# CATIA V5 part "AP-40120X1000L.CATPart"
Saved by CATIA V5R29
Part number: AP-40120X1000L
Bounding box of the stored display mesh (mm): x -500 to 500, y -60 to 60, z -20 to 20
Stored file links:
  C:\Users\Administrator\Desktop\프로젝트\Boxfold\AP-40120X1000L.CATPart
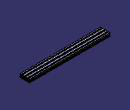
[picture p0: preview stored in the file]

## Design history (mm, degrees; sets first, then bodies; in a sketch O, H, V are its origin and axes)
Body1 (main body)
  Sketch1 on yz-plane, origin (0, 0, 0), H (0, 1, 0), V (0, 0, 1)
    point P1 (-60, -19)
    circle A1 centre (53.5, -13.5) radius 4
    circle A2 centre (53.5, 13.5) radius 4
    circle A3 centre (-53.5, -13.5) radius 4
    circle A4 centre (-53.5, 13.5) radius 4
    arc A5 centre (-38.0088, -3.1185) radius 0.3 from (-37.7966, -2.9064) to (-38.1702, -2.8656) ccw
    line L1 (-37.7966, -2.9064) -> (-37.1018, -3.6012)
    arc A6 centre (-36.8897, -3.3891) radius 0.3 from (-37.1018, -3.6012) to (-36.6868, -3.6101) ccw
    arc A7 centre (-40, 0) radius 4.9 from (-36.6868, -3.6101) to (-36.3857, -3.3086) ccw
    arc A8 centre (-36.607, -3.106) radius 0.3 from (-36.3857, -3.3086) to (-36.3949, -2.8939) ccw
    line L2 (-36.3949, -2.8939) -> (-37.0904, -2.1983)
    arc A9 centre (-36.8783, -1.9862) radius 0.3 from (-37.1314, -1.8252) to (-37.0904, -2.1983) ccw
    arc A10 centre (-40, 0) radius 3.4 from (-37.1314, -1.8252) to (-37.1323, 1.8265) ccw
    arc A11 centre (-36.8792, 1.9877) radius 0.3 from (-37.0914, 2.1998) to (-37.1323, 1.8265) ccw
    line L3 (-37.0914, 2.1998) -> (-36.396, 2.8952)
    arc A12 centre (-36.6081, 3.1073) radius 0.3 from (-36.396, 2.8952) to (-36.3869, 3.31) ccw
    arc A13 centre (-40, 0) radius 4.9 from (-36.3869, 3.31) to (-36.6881, 3.6113) ccw
    arc A14 centre (-36.8909, 3.3902) radius 0.3 from (-36.6881, 3.6113) to (-37.103, 3.6024) ccw
    line L4 (-37.103, 3.6024) -> (-37.7981, 2.9073)
    arc A15 centre (-38.0102, 3.1194) radius 0.3 from (-38.1716, 2.8665) to (-37.7981, 2.9073) ccw
    arc A16 centre (-40, 0) radius 3.4 from (-38.1716, 2.8665) to (-41.8252, 2.8686) ccw
    arc A17 centre (-41.9862, 3.1217) radius 0.3 from (-42.1983, 2.9096) to (-41.8252, 2.8686) ccw
    line L5 (-42.1983, 2.9096) -> (-42.8939, 3.6051)
    arc A18 centre (-43.106, 3.393) radius 0.3 from (-42.8939, 3.6051) to (-43.3086, 3.6143) ccw
    arc A19 centre (-40, 0) radius 4.9 from (-43.3086, 3.6143) to (-43.6101, 3.3132) ccw
    arc A20 centre (-43.3891, 3.1103) radius 0.3 from (-43.6101, 3.3132) to (-43.6012, 2.8982) ccw
    line L6 (-43.6012, 2.8982) -> (-42.9064, 2.2034)
    arc A21 centre (-43.1185, 1.9912) radius 0.3 from (-42.8656, 1.8298) to (-42.9064, 2.2034) ccw
    arc A22 centre (-40, 0) radius 3.4 from (-42.8656, 1.8298) to (-42.8665, -1.8284) ccw
    arc A23 centre (-43.1194, -1.9898) radius 0.3 from (-42.9073, -2.2019) to (-42.8665, -1.8284) ccw
    line L7 (-42.9073, -2.2019) -> (-43.6024, -2.897)
    arc A24 centre (-43.3902, -3.1091) radius 0.3 from (-43.6024, -2.897) to (-43.6113, -3.3119) ccw
    arc A25 centre (-40, 0) radius 4.9 from (-43.6113, -3.3119) to (-43.31, -3.6131) ccw
    arc A26 centre (-43.1073, -3.3919) radius 0.3 from (-43.31, -3.6131) to (-42.8952, -3.604) ccw
    line L8 (-42.8952, -3.604) -> (-42.1998, -2.9086)
    arc A27 centre (-41.9877, -3.1208) radius 0.3 from (-41.8265, -2.8677) to (-42.1998, -2.9086) ccw
    arc A28 centre (-40, 0) radius 3.4 from (-41.8265, -2.8677) to (-38.1702, -2.8656) ccw
    line L9 (39.6951, 6.0049) -> (40, 5.7)
    line L10 (40, 5.7) -> (40.3049, 6.0049)
    arc A29 centre (40, 15.5) radius 9.5 from (40.3049, 6.0049) to (47.0734, 9.1583) ccw
    arc A30 centre (46.85, 9.3585) radius 0.3 from (47.0734, 9.1583) to (47.15, 9.3585) ccw
    line L11 (47.15, 9.3585) -> (47.15, 15.7)
    arc A31 centre (46.85, 15.7) radius 0.3 from (47.15, 15.7) to (46.85, 16) ccw
    line L12 (46.85, 16) -> (44.65, 16)
    arc A32 centre (44.65, 16.5) radius 0.5 from (44.15, 16.5) to (44.65, 16) ccw
    line L13 (44.15, 16.5) -> (44.15, 19.5)
    arc A33 centre (44.65, 19.5) radius 0.5 from (44.65, 20) to (44.15, 19.5) ccw
    line L14 (44.65, 20) -> (59, 20)
    arc A34 centre (59, 19) radius 1 from (60, 19) to (59, 20) ccw
    line L15 (60, 19) -> (60, 4.65)
    arc A35 centre (59.5, 4.65) radius 0.5 from (59.5, 4.15) to (60, 4.65) ccw
    line L16 (59.5, 4.15) -> (56.5, 4.15)
    arc A36 centre (56.5, 4.65) radius 0.5 from (56, 4.65) to (56.5, 4.15) ccw
    line L17 (56, 4.65) -> (56, 6.85)
    arc A37 centre (55.7, 6.85) radius 0.3 from (56, 6.85) to (55.7, 7.15) ccw
    line L18 (55.7, 7.15) -> (49.3585, 7.15)
    arc A38 centre (49.3585, 6.85) radius 0.3 from (49.3585, 7.15) to (49.1583, 7.0734) ccw
    arc A39 centre (55.5, 0) radius 9.5 from (49.1583, 7.0734) to (46.0049, 0.3049) ccw
    line L19 (46.0049, 0.3049) -> (45.7, 0)
    line L20 (45.7, 0) -> (46.0049, -0.3049)
    arc A40 centre (55.5, 0) radius 9.5 from (46.0049, -0.3049) to (49.1583, -7.0734) ccw
    arc A41 centre (49.3585, -6.85) radius 0.3 from (49.1583, -7.0734) to (49.3585, -7.15) ccw
    line L21 (49.3585, -7.15) -> (55.7, -7.15)
    arc A42 centre (55.7, -6.85) radius 0.3 from (55.7, -7.15) to (56, -6.85) ccw
    line L22 (56, -6.85) -> (56, -4.65)
    arc A43 centre (56.5, -4.65) radius 0.5 from (56.5, -4.15) to (56, -4.65) ccw
    line L23 (56.5, -4.15) -> (59.5, -4.15)
    arc A44 centre (59.5, -4.65) radius 0.5 from (60, -4.65) to (59.5, -4.15) ccw
    line L24 (60, -4.65) -> (60, -19)
    arc A45 centre (59, -19) radius 1 from (59, -20) to (60, -19) ccw
    line L25 (59, -20) -> (44.65, -20)
    arc A46 centre (44.65, -19.5) radius 0.5 from (44.15, -19.5) to (44.65, -20) ccw
    line L26 (44.15, -19.5) -> (44.15, -16.5)
    arc A47 centre (44.65, -16.5) radius 0.5 from (44.65, -16) to (44.15, -16.5) ccw
    line L27 (44.65, -16) -> (46.85, -16)
    arc A48 centre (46.85, -15.7) radius 0.3 from (46.85, -16) to (47.15, -15.7) ccw
    line L28 (47.15, -15.7) -> (47.15, -9.3585)
    arc A49 centre (46.85, -9.3585) radius 0.3 from (47.15, -9.3585) to (47.0734, -9.1583) ccw
    arc A50 centre (40, -15.5) radius 9.5 from (47.0734, -9.1583) to (40.3049, -6.0049) ccw
    line L29 (40.3049, -6.0049) -> (40, -5.7)
    line L30 (40, -5.7) -> (39.6951, -6.0049)
    arc A51 centre (40, -15.5) radius 9.5 from (39.6951, -6.0049) to (32.9266, -9.1583) ccw
    arc A52 centre (33.15, -9.3585) radius 0.3 from (32.9266, -9.1583) to (32.85, -9.3585) ccw
    line L31 (32.85, -9.3585) -> (32.85, -15.7)
    arc A53 centre (33.15, -15.7) radius 0.3 from (32.85, -15.7) to (33.15, -16) ccw
    line L32 (33.15, -16) -> (35.35, -16)
    arc A54 centre (35.35, -16.5) radius 0.5 from (35.85, -16.5) to (35.35, -16) ccw
    line L33 (35.85, -16.5) -> (35.85, -19.5)
    arc A55 centre (35.35, -19.5) radius 0.5 from (35.35, -20) to (35.85, -19.5) ccw
    line L34 (35.35, -20) -> (4.65, -20)
    arc A56 centre (4.65, -19.5) radius 0.5 from (4.15, -19.5) to (4.65, -20) ccw
    line L35 (4.15, -19.5) -> (4.15, -16.5)
    arc A57 centre (4.65, -16.5) radius 0.5 from (4.65, -16) to (4.15, -16.5) ccw
    line L36 (4.65, -16) -> (6.85, -16)
    arc A58 centre (6.85, -15.7) radius 0.3 from (6.85, -16) to (7.15, -15.7) ccw
    line L37 (7.15, -15.7) -> (7.15, -9.3585)
    arc A59 centre (6.85, -9.3585) radius 0.3 from (7.15, -9.3585) to (7.0734, -9.1583) ccw
    arc A60 centre (0, -15.5) radius 9.5 from (7.0734, -9.1583) to (0.3049, -6.0049) ccw
    line L38 (0.3049, -6.0049) -> (0, -5.7)
    line L39 (0, -5.7) -> (-0.3049, -6.0049)
    arc A61 centre (0, -15.5) radius 9.5 from (-0.3049, -6.0049) to (-7.0734, -9.1583) ccw
    arc A62 centre (-6.85, -9.3585) radius 0.3 from (-7.0734, -9.1583) to (-7.15, -9.3585) ccw
    line L40 (-7.15, -9.3585) -> (-7.15, -15.7)
    arc A63 centre (-6.85, -15.7) radius 0.3 from (-7.15, -15.7) to (-6.85, -16) ccw
    line L41 (-6.85, -16) -> (-4.65, -16)
    arc A64 centre (-4.65, -16.5) radius 0.5 from (-4.15, -16.5) to (-4.65, -16) ccw
    line L42 (-4.15, -16.5) -> (-4.15, -19.5)
    arc A65 centre (-4.65, -19.5) radius 0.5 from (-4.65, -20) to (-4.15, -19.5) ccw
    line L43 (-4.65, -20) -> (-35.35, -20)
    arc A66 centre (-35.35, -19.5) radius 0.5 from (-35.85, -19.5) to (-35.35, -20) ccw
    line L44 (-35.85, -19.5) -> (-35.85, -16.5)
    arc A67 centre (-35.35, -16.5) radius 0.5 from (-35.35, -16) to (-35.85, -16.5) ccw
    line L45 (-35.35, -16) -> (-33.15, -16)
    arc A68 centre (-33.15, -15.7) radius 0.3 from (-33.15, -16) to (-32.85, -15.7) ccw
    line L46 (-32.85, -15.7) -> (-32.85, -9.3585)
    arc A69 centre (-33.15, -9.3585) radius 0.3 from (-32.85, -9.3585) to (-32.9266, -9.1583) ccw
    arc A70 centre (-40, -15.5) radius 9.5 from (-32.9266, -9.1583) to (-39.6951, -6.0049) ccw
    line L47 (-39.6951, -6.0049) -> (-40, -5.7)
    line L48 (-40, -5.7) -> (-40.3049, -6.0049)
    arc A71 centre (-40, -15.5) radius 9.5 from (-40.3049, -6.0049) to (-47.0734, -9.1583) ccw
    arc A72 centre (-46.85, -9.3585) radius 0.3 from (-47.0734, -9.1583) to (-47.15, -9.3585) ccw
    line L49 (-47.15, -9.3585) -> (-47.15, -15.7)
    arc A73 centre (-46.85, -15.7) radius 0.3 from (-47.15, -15.7) to (-46.85, -16) ccw
    line L50 (-46.85, -16) -> (-44.65, -16)
    arc A74 centre (-44.65, -16.5) radius 0.5 from (-44.15, -16.5) to (-44.65, -16) ccw
    line L51 (-44.15, -16.5) -> (-44.15, -19.5)
    arc A75 centre (-44.65, -19.5) radius 0.5 from (-44.65, -20) to (-44.15, -19.5) ccw
    line L52 (-44.65, -20) -> (-58, -20)
    line L53 (-58, -20) -> (-59, -20)
    arc A76 centre (-59, -19) radius 1 from (-60, -19) to (-59, -20) ccw
    line L54 (-60, -19) -> (-60, -4.65)
    arc A77 centre (-59.5, -4.65) radius 0.5 from (-59.5, -4.15) to (-60, -4.65) ccw
    line L55 (-59.5, -4.15) -> (-56.5, -4.15)
    arc A78 centre (-56.5, -4.65) radius 0.5 from (-56, -4.65) to (-56.5, -4.15) ccw
    line L56 (-56, -4.65) -> (-56, -6.85)
    arc A79 centre (-55.7, -6.85) radius 0.3 from (-56, -6.85) to (-55.7, -7.15) ccw
    line L57 (-55.7, -7.15) -> (-49.3585, -7.15)
    arc A80 centre (-49.3585, -6.85) radius 0.3 from (-49.3585, -7.15) to (-49.1583, -7.0734) ccw
    arc A81 centre (-55.5, 0) radius 9.5 from (-49.1583, -7.0734) to (-46.0049, -0.3049) ccw
    line L58 (-46.0049, -0.3049) -> (-45.7, 0)
    line L59 (-45.7, 0) -> (-46.0049, 0.3049)
    arc A82 centre (-55.5, 0) radius 9.5 from (-46.0049, 0.3049) to (-49.1583, 7.0734) ccw
    arc A83 centre (-49.3585, 6.85) radius 0.3 from (-49.1583, 7.0734) to (-49.3585, 7.15) ccw
    line L60 (-49.3585, 7.15) -> (-55.7, 7.15)
    arc A84 centre (-55.7, 6.85) radius 0.3 from (-55.7, 7.15) to (-56, 6.85) ccw
    line L61 (-56, 6.85) -> (-56, 4.65)
    arc A85 centre (-56.5, 4.65) radius 0.5 from (-56.5, 4.15) to (-56, 4.65) ccw
    line L62 (-56.5, 4.15) -> (-59.5, 4.15)
    arc A86 centre (-59.5, 4.65) radius 0.5 from (-60, 4.65) to (-59.5, 4.15) ccw
    line L63 (-60, 4.65) -> (-60, 19)
    arc A87 centre (-59, 19) radius 1 from (-59, 20) to (-60, 19) ccw
    line L64 (-59, 20) -> (-58, 20)
    line L65 (-58, 20) -> (-44.65, 20)
    arc A88 centre (-44.65, 19.5) radius 0.5 from (-44.15, 19.5) to (-44.65, 20) ccw
    line L66 (-44.15, 19.5) -> (-44.15, 16.5)
    arc A89 centre (-44.65, 16.5) radius 0.5 from (-44.65, 16) to (-44.15, 16.5) ccw
    line L67 (-44.65, 16) -> (-46.85, 16)
    arc A90 centre (-46.85, 15.7) radius 0.3 from (-46.85, 16) to (-47.15, 15.7) ccw
    line L68 (-47.15, 15.7) -> (-47.15, 9.3585)
    arc A91 centre (-46.85, 9.3585) radius 0.3 from (-47.15, 9.3585) to (-47.0734, 9.1583) ccw
    arc A92 centre (-40, 15.5) radius 9.5 from (-47.0734, 9.1583) to (-40.3049, 6.0049) ccw
    line L69 (-40.3049, 6.0049) -> (-40, 5.7)
    line L70 (-40, 5.7) -> (-39.6951, 6.0049)
    arc A93 centre (-40, 15.5) radius 9.5 from (-39.6951, 6.0049) to (-32.9266, 9.1583) ccw
    arc A94 centre (-33.15, 9.3585) radius 0.3 from (-32.9266, 9.1583) to (-32.85, 9.3585) ccw
    line L71 (-32.85, 9.3585) -> (-32.85, 15.7)
    arc A95 centre (-33.15, 15.7) radius 0.3 from (-32.85, 15.7) to (-33.15, 16) ccw
    line L72 (-33.15, 16) -> (-35.35, 16)
    arc A96 centre (-35.35, 16.5) radius 0.5 from (-35.85, 16.5) to (-35.35, 16) ccw
    line L73 (-35.85, 16.5) -> (-35.85, 19.5)
    arc A97 centre (-35.35, 19.5) radius 0.5 from (-35.35, 20) to (-35.85, 19.5) ccw
    line L74 (-35.35, 20) -> (-4.65, 20)
    arc A98 centre (-4.65, 19.5) radius 0.5 from (-4.15, 19.5) to (-4.65, 20) ccw
    line L75 (-4.15, 19.5) -> (-4.15, 16.5)
    arc A99 centre (-4.65, 16.5) radius 0.5 from (-4.65, 16) to (-4.15, 16.5) ccw
    line L76 (-4.65, 16) -> (-6.85, 16)
    arc A100 centre (-6.85, 15.7) radius 0.3 from (-6.85, 16) to (-7.15, 15.7) ccw
    line L77 (-7.15, 15.7) -> (-7.15, 9.3585)
    arc A101 centre (-6.85, 9.3585) radius 0.3 from (-7.15, 9.3585) to (-7.0734, 9.1583) ccw
    arc A102 centre (0, 15.5) radius 9.5 from (-7.0734, 9.1583) to (-0.3049, 6.0049) ccw
    line L78 (-0.3049, 6.0049) -> (0, 5.7)
    line L79 (0, 5.7) -> (0.3049, 6.0049)
    arc A103 centre (0, 15.5) radius 9.5 from (0.3049, 6.0049) to (7.0734, 9.1583) ccw
    arc A104 centre (6.85, 9.3585) radius 0.3 from (7.0734, 9.1583) to (7.15, 9.3585) ccw
    line L80 (7.15, 9.3585) -> (7.15, 15.7)
    arc A105 centre (6.85, 15.7) radius 0.3 from (7.15, 15.7) to (6.85, 16) ccw
    line L81 (6.85, 16) -> (4.65, 16)
    arc A106 centre (4.65, 16.5) radius 0.5 from (4.15, 16.5) to (4.65, 16) ccw
    line L82 (4.15, 16.5) -> (4.15, 19.5)
    arc A107 centre (4.65, 19.5) radius 0.5 from (4.65, 20) to (4.15, 19.5) ccw
    line L83 (4.65, 20) -> (35.35, 20)
    arc A108 centre (35.35, 19.5) radius 0.5 from (35.85, 19.5) to (35.35, 20) ccw
    line L84 (35.85, 19.5) -> (35.85, 16.5)
    arc A109 centre (35.35, 16.5) radius 0.5 from (35.35, 16) to (35.85, 16.5) ccw
    line L85 (35.35, 16) -> (33.15, 16)
    arc A110 centre (33.15, 15.7) radius 0.3 from (33.15, 16) to (32.85, 15.7) ccw
    line L86 (32.85, 15.7) -> (32.85, 9.3585)
    arc A111 centre (33.15, 9.3585) radius 0.3 from (32.85, 9.3585) to (32.9266, 9.1583) ccw
    arc A112 centre (40, 15.5) radius 9.5 from (32.9266, 9.1583) to (39.6951, 6.0049) ccw
    arc A113 centre (13.15, -14) radius 3 from (10.15, -14) to (13.15, -17) ccw
    line L87 (13.15, -17) -> (26.85, -17)
    arc A114 centre (26.85, -14) radius 3 from (26.85, -17) to (29.85, -14) ccw
    line L88 (29.85, -14) -> (29.85, -8.9422)
    arc A115 centre (20, -0.0053) radius 13.3 from (29.85, -8.9422) to (29.85, 8.9315) ccw
    line L89 (29.85, 8.9315) -> (29.85, 14)
    arc A116 centre (26.85, 14) radius 3 from (29.85, 14) to (26.85, 17) ccw
    line L90 (26.85, 17) -> (13.15, 17)
    arc A117 centre (13.15, 14) radius 3 from (13.15, 17) to (10.15, 14) ccw
    line L91 (10.15, 14) -> (10.15, 8.9315)
    arc A118 centre (20, -0.0053) radius 13.3 from (10.15, 8.9315) to (10.15, -8.9422) ccw
    line L92 (10.15, -8.9422) -> (10.15, -14)
    arc A119 centre (1.9912, -3.1185) radius 0.3 from (2.2034, -2.9064) to (1.8298, -2.8656) ccw
    line L93 (2.2034, -2.9064) -> (2.8982, -3.6012)
    arc A120 centre (3.1103, -3.3891) radius 0.3 from (2.8982, -3.6012) to (3.3132, -3.6101) ccw
    arc A121 centre (0, 0) radius 4.9 from (3.3132, -3.6101) to (3.6143, -3.3086) ccw
    arc A122 centre (3.393, -3.106) radius 0.3 from (3.6143, -3.3086) to (3.6051, -2.8939) ccw
    line L94 (3.6051, -2.8939) -> (2.9096, -2.1983)
    arc A123 centre (3.1217, -1.9862) radius 0.3 from (2.8686, -1.8252) to (2.9096, -2.1983) ccw
    arc A124 centre (0, 0) radius 3.4 from (2.8686, -1.8252) to (2.8677, 1.8265) ccw
    arc A125 centre (3.1208, 1.9877) radius 0.3 from (2.9086, 2.1998) to (2.8677, 1.8265) ccw
    line L95 (2.9086, 2.1998) -> (3.604, 2.8952)
    arc A126 centre (3.3919, 3.1073) radius 0.3 from (3.604, 2.8952) to (3.6131, 3.31) ccw
    arc A127 centre (0, 0) radius 4.9 from (3.6131, 3.31) to (3.3119, 3.6113) ccw
    arc A128 centre (3.1091, 3.3902) radius 0.3 from (3.3119, 3.6113) to (2.897, 3.6024) ccw
    line L96 (2.897, 3.6024) -> (2.2019, 2.9073)
    arc A129 centre (1.9898, 3.1194) radius 0.3 from (1.8284, 2.8665) to (2.2019, 2.9073) ccw
    arc A130 centre (0, 0) radius 3.4 from (1.8284, 2.8665) to (-1.8252, 2.8686) ccw
    arc A131 centre (-1.9862, 3.1217) radius 0.3 from (-2.1983, 2.9096) to (-1.8252, 2.8686) ccw
    line L97 (-2.1983, 2.9096) -> (-2.8939, 3.6051)
    arc A132 centre (-3.106, 3.393) radius 0.3 from (-2.8939, 3.6051) to (-3.3086, 3.6143) ccw
    arc A133 centre (0, 0) radius 4.9 from (-3.3086, 3.6143) to (-3.6101, 3.3132) ccw
    arc A134 centre (-3.3891, 3.1103) radius 0.3 from (-3.6101, 3.3132) to (-3.6012, 2.8982) ccw
    line L98 (-3.6012, 2.8982) -> (-2.9064, 2.2034)
    arc A135 centre (-3.1185, 1.9912) radius 0.3 from (-2.8656, 1.8298) to (-2.9064, 2.2034) ccw
    arc A136 centre (0, 0) radius 3.4 from (-2.8656, 1.8298) to (-2.8665, -1.8284) ccw
    arc A137 centre (-3.1194, -1.9898) radius 0.3 from (-2.9073, -2.2019) to (-2.8665, -1.8284) ccw
    line L99 (-2.9073, -2.2019) -> (-3.6024, -2.897)
    arc A138 centre (-3.3902, -3.1091) radius 0.3 from (-3.6024, -2.897) to (-3.6113, -3.3119) ccw
    arc A139 centre (0, 0) radius 4.9 from (-3.6113, -3.3119) to (-3.31, -3.6131) ccw
    arc A140 centre (-3.1073, -3.3919) radius 0.3 from (-3.31, -3.6131) to (-2.8952, -3.604) ccw
    line L100 (-2.8952, -3.604) -> (-2.1998, -2.9086)
    arc A141 centre (-1.9877, -3.1208) radius 0.3 from (-1.8265, -2.8677) to (-2.1998, -2.9086) ccw
    arc A142 centre (0, 0) radius 3.4 from (-1.8265, -2.8677) to (1.8298, -2.8656) ccw
    arc A143 centre (41.9912, -3.1185) radius 0.3 from (42.2034, -2.9064) to (41.8298, -2.8656) ccw
    line L101 (42.2034, -2.9064) -> (42.8982, -3.6012)
    arc A144 centre (43.1103, -3.3891) radius 0.3 from (42.8982, -3.6012) to (43.3132, -3.6101) ccw
    arc A145 centre (40, 0) radius 4.9 from (43.3132, -3.6101) to (43.6143, -3.3086) ccw
    arc A146 centre (43.393, -3.106) radius 0.3 from (43.6143, -3.3086) to (43.6051, -2.8939) ccw
    line L102 (43.6051, -2.8939) -> (42.9096, -2.1983)
    arc A147 centre (43.1217, -1.9862) radius 0.3 from (42.8686, -1.8252) to (42.9096, -2.1983) ccw
    arc A148 centre (40, 0) radius 3.4 from (42.8686, -1.8252) to (42.8677, 1.8265) ccw
    arc A149 centre (43.1208, 1.9877) radius 0.3 from (42.9086, 2.1998) to (42.8677, 1.8265) ccw
    line L103 (42.9086, 2.1998) -> (43.604, 2.8952)
    arc A150 centre (43.3919, 3.1073) radius 0.3 from (43.604, 2.8952) to (43.6131, 3.31) ccw
    arc A151 centre (40, 0) radius 4.9 from (43.6131, 3.31) to (43.3119, 3.6113) ccw
    arc A152 centre (43.1091, 3.3902) radius 0.3 from (43.3119, 3.6113) to (42.897, 3.6024) ccw
    line L104 (42.897, 3.6024) -> (42.2019, 2.9073)
    arc A153 centre (41.9898, 3.1194) radius 0.3 from (41.8284, 2.8665) to (42.2019, 2.9073) ccw
    arc A154 centre (40, 0) radius 3.4 from (41.8284, 2.8665) to (38.1748, 2.8686) ccw
    arc A155 centre (38.0138, 3.1217) radius 0.3 from (37.8017, 2.9096) to (38.1748, 2.8686) ccw
    line L105 (37.8017, 2.9096) -> (37.1061, 3.6051)
    arc A156 centre (36.894, 3.393) radius 0.3 from (37.1061, 3.6051) to (36.6914, 3.6143) ccw
    arc A157 centre (40, 0) radius 4.9 from (36.6914, 3.6143) to (36.3899, 3.3132) ccw
    arc A158 centre (36.6109, 3.1103) radius 0.3 from (36.3899, 3.3132) to (36.3988, 2.8982) ccw
    line L106 (36.3988, 2.8982) -> (37.0936, 2.2034)
    arc A159 centre (36.8815, 1.9912) radius 0.3 from (37.1344, 1.8298) to (37.0936, 2.2034) ccw
    arc A160 centre (40, 0) radius 3.4 from (37.1344, 1.8298) to (37.1335, -1.8284) ccw
    arc A161 centre (36.8806, -1.9898) radius 0.3 from (37.0927, -2.2019) to (37.1335, -1.8284) ccw
    line L107 (37.0927, -2.2019) -> (36.3976, -2.897)
    arc A162 centre (36.6098, -3.1091) radius 0.3 from (36.3976, -2.897) to (36.3887, -3.3119) ccw
    arc A163 centre (40, 0) radius 4.9 from (36.3887, -3.3119) to (36.69, -3.6131) ccw
    arc A164 centre (36.8927, -3.3919) radius 0.3 from (36.69, -3.6131) to (37.1048, -3.604) ccw
    line L108 (37.1048, -3.604) -> (37.8002, -2.9086)
    arc A165 centre (38.0123, -3.1208) radius 0.3 from (38.1735, -2.8677) to (37.8002, -2.9086) ccw
    arc A166 centre (40, 0) radius 3.4 from (38.1735, -2.8677) to (41.8298, -2.8656) ccw
    line L109 (-13.15, 17) -> (-26.85, 17)
    arc A167 centre (-26.85, 14) radius 3 from (-26.85, 17) to (-29.85, 14) ccw
    line L110 (-29.85, 14) -> (-29.85, 8.9315)
    arc A168 centre (-20, -0.0053) radius 13.3 from (-29.85, 8.9315) to (-29.85, -8.9422) ccw
    line L111 (-29.85, -8.9422) -> (-29.85, -14)
    arc A169 centre (-26.85, -14) radius 3 from (-29.85, -14) to (-26.85, -17) ccw
    line L112 (-26.85, -17) -> (-13.15, -17)
    arc A170 centre (-13.15, -14) radius 3 from (-13.15, -17) to (-10.15, -14) ccw
    line L113 (-10.15, -14) -> (-10.15, -8.9422)
    arc A171 centre (-20, -0.0053) radius 13.3 from (-10.15, -8.9422) to (-10.15, 8.9315) ccw
    line L114 (-10.15, 8.9315) -> (-10.15, 14)
    arc A172 centre (-13.15, 14) radius 3 from (-10.15, 14) to (-13.15, 17) ccw
    point P2 (-37.7966, -2.9064)
    point P3 (-38.1702, -2.8656)
    point P4 (-37.7966, -2.9064)
    point P5 (-37.1018, -3.6012)
    point P6 (-37.1018, -3.6012)
    point P7 (-36.6868, -3.6101)
    point P8 (-36.6868, -3.6101)
    point P9 (-36.3857, -3.3086)
    point P10 (-36.3857, -3.3086)
    point P11 (-36.3949, -2.8939)
    point P12 (-36.3949, -2.8939)
    point P13 (-37.0904, -2.1983)
    point P14 (-37.1314, -1.8252)
    point P15 (-37.0904, -2.1983)
    point P16 (-37.1314, -1.8252)
    point P17 (-37.1323, 1.8265)
    point P18 (-37.0914, 2.1998)
    point P19 (-37.1323, 1.8265)
    point P20 (-37.0914, 2.1998)
    point P21 (-36.396, 2.8952)
    point P22 (-36.396, 2.8952)
    point P23 (-36.3869, 3.31)
    point P24 (-36.3869, 3.31)
    point P25 (-36.6881, 3.6113)
    point P26 (-36.6881, 3.6113)
    point P27 (-37.103, 3.6024)
    point P28 (-37.103, 3.6024)
    point P29 (-37.7981, 2.9073)
    point P30 (-38.1716, 2.8665)
    point P31 (-37.7981, 2.9073)
    point P32 (-38.1716, 2.8665)
    point P33 (-41.8252, 2.8686)
    point P34 (-42.1983, 2.9096)
    point P35 (-41.8252, 2.8686)
    point P36 (-42.1983, 2.9096)
    point P37 (-42.8939, 3.6051)
    point P38 (-42.8939, 3.6051)
    point P39 (-43.3086, 3.6143)
    point P40 (-43.3086, 3.6143)
    point P41 (-43.6101, 3.3132)
    point P42 (-43.6101, 3.3132)
    point P43 (-43.6012, 2.8982)
    point P44 (-43.6012, 2.8982)
    point P45 (-42.9064, 2.2034)
    point P46 (-42.8656, 1.8298)
    point P47 (-42.9064, 2.2034)
    point P48 (-42.8656, 1.8298)
    point P49 (-42.8665, -1.8284)
    point P50 (-42.9073, -2.2019)
    point P51 (-42.8665, -1.8284)
    point P52 (-42.9073, -2.2019)
    point P53 (-43.6024, -2.897)
    point P54 (-43.6024, -2.897)
    point P55 (-43.6113, -3.3119)
    point P56 (-43.6113, -3.3119)
    point P57 (-43.31, -3.6131)
    point P58 (-43.31, -3.6131)
    point P59 (-42.8952, -3.604)
    point P60 (-42.8952, -3.604)
    point P61 (-42.1998, -2.9086)
    point P62 (-41.8265, -2.8677)
    point P63 (-42.1998, -2.9086)
    point P64 (-41.8265, -2.8677)
    point P65 (-38.1702, -2.8656)
    point P66 (39.6951, 6.0049)
    point P67 (40, 5.7)
    point P68 (40, 5.7)
    point P69 (40.3049, 6.0049)
    point P70 (40.3049, 6.0049)
    point P71 (47.0734, 9.1583)
    point P72 (47.0734, 9.1583)
    point P73 (47.15, 9.3585)
    point P74 (47.15, 9.3585)
    point P75 (47.15, 15.7)
    point P76 (47.15, 15.7)
    point P77 (46.85, 16)
    point P78 (46.85, 16)
    point P79 (44.65, 16)
    point P80 (44.15, 16.5)
    point P81 (44.65, 16)
    point P82 (44.15, 16.5)
    point P83 (44.15, 19.5)
    point P84 (44.65, 20)
    point P85 (44.15, 19.5)
    point P86 (44.65, 20)
    point P87 (59, 20)
    point P88 (60, 19)
    point P89 (59, 20)
    point P90 (60, 19)
    point P91 (60, 4.65)
    point P92 (59.5, 4.15)
    point P93 (60, 4.65)
    point P94 (59.5, 4.15)
    point P95 (56.5, 4.15)
    point P96 (56, 4.65)
    point P97 (56.5, 4.15)
    point P98 (56, 4.65)
    point P99 (56, 6.85)
    point P100 (56, 6.85)
    point P101 (55.7, 7.15)
    point P102 (55.7, 7.15)
    point P103 (49.3585, 7.15)
    point P104 (49.3585, 7.15)
    point P105 (49.1583, 7.0734)
    point P106 (49.1583, 7.0734)
    point P107 (46.0049, 0.3049)
    point P108 (46.0049, 0.3049)
    point P109 (45.7, 0)
    point P110 (45.7, 0)
    point P111 (46.0049, -0.3049)
    point P112 (46.0049, -0.3049)
    point P113 (49.1583, -7.0734)
    point P114 (49.1583, -7.0734)
    point P115 (49.3585, -7.15)
    point P116 (49.3585, -7.15)
    point P117 (55.7, -7.15)
    point P118 (55.7, -7.15)
    point P119 (56, -6.85)
    point P120 (56, -6.85)
    point P121 (56, -4.65)
    point P122 (56.5, -4.15)
    point P123 (56, -4.65)
    point P124 (56.5, -4.15)
    point P125 (59.5, -4.15)
    point P126 (60, -4.65)
    point P127 (59.5, -4.15)
    point P128 (60, -4.65)
    point P129 (60, -19)
    point P130 (59, -20)
    point P131 (60, -19)
    point P132 (59, -20)
    point P133 (44.65, -20)
    point P134 (44.15, -19.5)
    point P135 (44.65, -20)
    point P136 (44.15, -19.5)
    point P137 (44.15, -16.5)
    point P138 (44.65, -16)
    point P139 (44.15, -16.5)
    point P140 (44.65, -16)
    point P141 (46.85, -16)
    point P142 (46.85, -16)
    point P143 (47.15, -15.7)
    point P144 (47.15, -15.7)
    point P145 (47.15, -9.3585)
    point P146 (47.15, -9.3585)
    point P147 (47.0734, -9.1583)
    point P148 (47.0734, -9.1583)
    point P149 (40.3049, -6.0049)
    point P150 (40.3049, -6.0049)
    point P151 (40, -5.7)
    point P152 (40, -5.7)
    point P153 (39.6951, -6.0049)
    point P154 (39.6951, -6.0049)
    point P155 (32.9266, -9.1583)
    point P156 (32.9266, -9.1583)
    point P157 (32.85, -9.3585)
    point P158 (32.85, -9.3585)
    point P159 (32.85, -15.7)
    point P160 (32.85, -15.7)
    point P161 (33.15, -16)
    point P162 (33.15, -16)
    point P163 (35.35, -16)
    point P164 (35.85, -16.5)
    point P165 (35.35, -16)
    point P166 (35.85, -16.5)
    point P167 (35.85, -19.5)
    point P168 (35.35, -20)
    point P169 (35.85, -19.5)
    point P170 (35.35, -20)
    point P171 (4.65, -20)
    point P172 (4.15, -19.5)
    point P173 (4.65, -20)
    point P174 (4.15, -19.5)
    point P175 (4.15, -16.5)
    point P176 (4.65, -16)
    point P177 (4.15, -16.5)
    point P178 (4.65, -16)
    point P179 (6.85, -16)
    point P180 (6.85, -16)
    point P181 (7.15, -15.7)
    point P182 (7.15, -15.7)
    point P183 (7.15, -9.3585)
    point P184 (7.15, -9.3585)
    point P185 (7.0734, -9.1583)
    point P186 (7.0734, -9.1583)
    point P187 (0.3049, -6.0049)
    point P188 (0.3049, -6.0049)
    point P189 (0, -5.7)
    point P190 (0, -5.7)
    point P191 (-0.3049, -6.0049)
    point P192 (-0.3049, -6.0049)
    point P193 (-7.0734, -9.1583)
    point P194 (-7.0734, -9.1583)
    point P195 (-7.15, -9.3585)
    point P196 (-7.15, -9.3585)
    point P197 (-7.15, -15.7)
    point P198 (-7.15, -15.7)
    point P199 (-6.85, -16)
    point P200 (-6.85, -16)
    point P201 (-4.65, -16)
    point P202 (-4.15, -16.5)
    point P203 (-4.65, -16)
    point P204 (-4.15, -16.5)
    point P205 (-4.15, -19.5)
    point P206 (-4.65, -20)
    point P207 (-4.15, -19.5)
    point P208 (-4.65, -20)
    point P209 (-35.35, -20)
    point P210 (-35.85, -19.5)
    point P211 (-35.35, -20)
    point P212 (-35.85, -19.5)
    point P213 (-35.85, -16.5)
    point P214 (-35.35, -16)
    point P215 (-35.85, -16.5)
    point P216 (-35.35, -16)
    point P217 (-33.15, -16)
    point P218 (-33.15, -16)
    point P219 (-32.85, -15.7)
    point P220 (-32.85, -15.7)
    point P221 (-32.85, -9.3585)
    point P222 (-32.85, -9.3585)
    point P223 (-32.9266, -9.1583)
    point P224 (-32.9266, -9.1583)
    point P225 (-39.6951, -6.0049)
    point P226 (-39.6951, -6.0049)
    point P227 (-40, -5.7)
    point P228 (-40, -5.7)
    point P229 (-40.3049, -6.0049)
    point P230 (-40.3049, -6.0049)
    point P231 (-47.0734, -9.1583)
    point P232 (-47.0734, -9.1583)
    point P233 (-47.15, -9.3585)
    point P234 (-47.15, -9.3585)
    point P235 (-47.15, -15.7)
    point P236 (-47.15, -15.7)
    point P237 (-46.85, -16)
    point P238 (-46.85, -16)
    point P239 (-44.65, -16)
    point P240 (-44.15, -16.5)
    point P241 (-44.65, -16)
    point P242 (-44.15, -16.5)
    point P243 (-44.15, -19.5)
    point P244 (-44.65, -20)
    point P245 (-44.15, -19.5)
    point P246 (-44.65, -20)
    point P247 (-58, -20)
    point P248 (-58, -20)
    point P249 (-59, -20)
    point P250 (-60, -19)
    point P251 (-59, -20)
    point P252 (-60, -19)
    point P253 (-60, -4.65)
    point P254 (-59.5, -4.15)
    point P255 (-60, -4.65)
    point P256 (-59.5, -4.15)
    point P257 (-56.5, -4.15)
    point P258 (-56, -4.65)
    point P259 (-56.5, -4.15)
    point P260 (-56, -4.65)
    point P261 (-56, -6.85)
    point P262 (-56, -6.85)
    point P263 (-55.7, -7.15)
    point P264 (-55.7, -7.15)
    point P265 (-49.3585, -7.15)
    point P266 (-49.3585, -7.15)
    point P267 (-49.1583, -7.0734)
    point P268 (-49.1583, -7.0734)
    point P269 (-46.0049, -0.3049)
    point P270 (-46.0049, -0.3049)
    point P271 (-45.7, 0)
    point P272 (-45.7, 0)
    point P273 (-46.0049, 0.3049)
    point P274 (-46.0049, 0.3049)
    point P275 (-49.1583, 7.0734)
    point P276 (-49.1583, 7.0734)
    point P277 (-49.3585, 7.15)
    point P278 (-49.3585, 7.15)
    point P279 (-55.7, 7.15)
    point P280 (-55.7, 7.15)
    point P281 (-56, 6.85)
    point P282 (-56, 6.85)
    point P283 (-56, 4.65)
    point P284 (-56.5, 4.15)
    point P285 (-56, 4.65)
    point P286 (-56.5, 4.15)
    point P287 (-59.5, 4.15)
    point P288 (-60, 4.65)
    point P289 (-59.5, 4.15)
    point P290 (-60, 4.65)
    point P291 (-60, 19)
    point P292 (-59, 20)
    point P293 (-60, 19)
    point P294 (-59, 20)
    point P295 (-58, 20)
    point P296 (-58, 20)
    point P297 (-44.65, 20)
    point P298 (-44.15, 19.5)
    point P299 (-44.65, 20)
    point P300 (-44.15, 19.5)
    point P301 (-44.15, 16.5)
    point P302 (-44.65, 16)
    point P303 (-44.15, 16.5)
    point P304 (-44.65, 16)
    point P305 (-46.85, 16)
    point P306 (-46.85, 16)
    point P307 (-47.15, 15.7)
    point P308 (-47.15, 15.7)
    point P309 (-47.15, 9.3585)
    point P310 (-47.15, 9.3585)
    point P311 (-47.0734, 9.1583)
    point P312 (-47.0734, 9.1583)
    point P313 (-40.3049, 6.0049)
    point P314 (-40.3049, 6.0049)
    point P315 (-40, 5.7)
    point P316 (-40, 5.7)
    point P317 (-39.6951, 6.0049)
    point P318 (-39.6951, 6.0049)
    point P319 (-32.9266, 9.1583)
    point P320 (-32.9266, 9.1583)
    point P321 (-32.85, 9.3585)
    point P322 (-32.85, 9.3585)
    point P323 (-32.85, 15.7)
    point P324 (-32.85, 15.7)
    point P325 (-33.15, 16)
    point P326 (-33.15, 16)
    point P327 (-35.35, 16)
    point P328 (-35.85, 16.5)
    point P329 (-35.35, 16)
    point P330 (-35.85, 16.5)
    point P331 (-35.85, 19.5)
    point P332 (-35.35, 20)
    point P333 (-35.85, 19.5)
    point P334 (-35.35, 20)
    point P335 (-4.65, 20)
    point P336 (-4.15, 19.5)
    point P337 (-4.65, 20)
    point P338 (-4.15, 19.5)
    point P339 (-4.15, 16.5)
    point P340 (-4.65, 16)
    point P341 (-4.15, 16.5)
    point P342 (-4.65, 16)
    point P343 (-6.85, 16)
    point P344 (-6.85, 16)
    point P345 (-7.15, 15.7)
    point P346 (-7.15, 15.7)
    point P347 (-7.15, 9.3585)
    point P348 (-7.15, 9.3585)
    point P349 (-7.0734, 9.1583)
    point P350 (-7.0734, 9.1583)
    point P351 (-0.3049, 6.0049)
    point P352 (-0.3049, 6.0049)
    point P353 (0, 5.7)
    point P354 (0, 5.7)
    point P355 (0.3049, 6.0049)
    point P356 (0.3049, 6.0049)
    point P357 (7.0734, 9.1583)
    point P358 (7.0734, 9.1583)
    point P359 (7.15, 9.3585)
    point P360 (7.15, 9.3585)
    point P361 (7.15, 15.7)
    point P362 (7.15, 15.7)
    point P363 (6.85, 16)
    point P364 (6.85, 16)
    point P365 (4.65, 16)
    point P366 (4.15, 16.5)
    point P367 (4.65, 16)
    point P368 (4.15, 16.5)
    point P369 (4.15, 19.5)
    point P370 (4.65, 20)
    point P371 (4.15, 19.5)
    point P372 (4.65, 20)
    point P373 (35.35, 20)
    point P374 (35.85, 19.5)
    point P375 (35.35, 20)
    point P376 (35.85, 19.5)
    point P377 (35.85, 16.5)
    point P378 (35.35, 16)
    point P379 (35.85, 16.5)
    point P380 (35.35, 16)
    point P381 (33.15, 16)
    point P382 (33.15, 16)
    point P383 (32.85, 15.7)
    point P384 (32.85, 15.7)
    point P385 (32.85, 9.3585)
    point P386 (32.85, 9.3585)
    point P387 (32.9266, 9.1583)
    point P388 (32.9266, 9.1583)
    point P389 (39.6951, 6.0049)
    point P390 (10.15, -14)
    point P391 (13.15, -17)
    point P392 (13.15, -17)
    point P393 (26.85, -17)
    point P394 (26.85, -17)
    point P395 (29.85, -14)
    point P396 (29.85, -14)
    point P397 (29.85, -8.9422)
    point P398 (29.85, -8.9422)
    point P399 (29.85, 8.9315)
    point P400 (29.85, 8.9315)
    point P401 (29.85, 14)
    point P402 (29.85, 14)
    point P403 (26.85, 17)
    point P404 (26.85, 17)
    point P405 (13.15, 17)
    point P406 (13.15, 17)
    point P407 (10.15, 14)
    point P408 (10.15, 14)
    point P409 (10.15, 8.9315)
    point P410 (10.15, 8.9315)
    point P411 (10.15, -8.9422)
    point P412 (10.15, -8.9422)
    point P413 (10.15, -14)
    point P414 (2.2034, -2.9064)
    point P415 (1.8298, -2.8656)
    point P416 (2.2034, -2.9064)
    point P417 (2.8982, -3.6012)
    point P418 (2.8982, -3.6012)
    point P419 (3.3132, -3.6101)
    point P420 (3.3132, -3.6101)
    point P421 (3.6143, -3.3086)
    point P422 (3.6143, -3.3086)
    point P423 (3.6051, -2.8939)
    point P424 (3.6051, -2.8939)
    point P425 (2.9096, -2.1983)
    point P426 (2.8686, -1.8252)
    point P427 (2.9096, -2.1983)
    point P428 (2.8686, -1.8252)
    point P429 (2.8677, 1.8265)
    point P430 (2.9086, 2.1998)
    point P431 (2.8677, 1.8265)
    point P432 (2.9086, 2.1998)
    point P433 (3.604, 2.8952)
    point P434 (3.604, 2.8952)
    point P435 (3.6131, 3.31)
    point P436 (3.6131, 3.31)
    point P437 (3.3119, 3.6113)
    point P438 (3.3119, 3.6113)
    point P439 (2.897, 3.6024)
    point P440 (2.897, 3.6024)
    point P441 (2.2019, 2.9073)
    point P442 (1.8284, 2.8665)
    point P443 (2.2019, 2.9073)
    point P444 (1.8284, 2.8665)
    point P445 (-1.8252, 2.8686)
    point P446 (-2.1983, 2.9096)
    point P447 (-1.8252, 2.8686)
    point P448 (-2.1983, 2.9096)
    point P449 (-2.8939, 3.6051)
    point P450 (-2.8939, 3.6051)
    point P451 (-3.3086, 3.6143)
    point P452 (-3.3086, 3.6143)
    point P453 (-3.6101, 3.3132)
    point P454 (-3.6101, 3.3132)
    point P455 (-3.6012, 2.8982)
    point P456 (-3.6012, 2.8982)
    point P457 (-2.9064, 2.2034)
    point P458 (-2.8656, 1.8298)
    point P459 (-2.9064, 2.2034)
    point P460 (-2.8656, 1.8298)
    point P461 (-2.8665, -1.8284)
    point P462 (-2.9073, -2.2019)
    point P463 (-2.8665, -1.8284)
    point P464 (-2.9073, -2.2019)
    point P465 (-3.6024, -2.897)
    point P466 (-3.6024, -2.897)
    point P467 (-3.6113, -3.3119)
    point P468 (-3.6113, -3.3119)
    point P469 (-3.31, -3.6131)
    point P470 (-3.31, -3.6131)
    point P471 (-2.8952, -3.604)
    point P472 (-2.8952, -3.604)
    point P473 (-2.1998, -2.9086)
    point P474 (-1.8265, -2.8677)
    point P475 (-2.1998, -2.9086)
    point P476 (-1.8265, -2.8677)
    point P477 (1.8298, -2.8656)
    point P478 (42.2034, -2.9064)
    point P479 (41.8298, -2.8656)
    point P480 (42.2034, -2.9064)
    point P481 (42.8982, -3.6012)
    point P482 (42.8982, -3.6012)
    point P483 (43.3132, -3.6101)
    point P484 (43.3132, -3.6101)
    point P485 (43.6143, -3.3086)
    point P486 (43.6143, -3.3086)
    point P487 (43.6051, -2.8939)
    point P488 (43.6051, -2.8939)
    point P489 (42.9096, -2.1983)
    point P490 (42.8686, -1.8252)
    point P491 (42.9096, -2.1983)
    point P492 (42.8686, -1.8252)
    point P493 (42.8677, 1.8265)
    point P494 (42.9086, 2.1998)
    point P495 (42.8677, 1.8265)
    point P496 (42.9086, 2.1998)
    point P497 (43.604, 2.8952)
    point P498 (43.604, 2.8952)
    point P499 (43.6131, 3.31)
    point P500 (43.6131, 3.31)
    point P501 (43.3119, 3.6113)
    point P502 (43.3119, 3.6113)
    point P503 (42.897, 3.6024)
    point P504 (42.897, 3.6024)
    point P505 (42.2019, 2.9073)
    point P506 (41.8284, 2.8665)
    point P507 (42.2019, 2.9073)
    point P508 (41.8284, 2.8665)
    point P509 (38.1748, 2.8686)
    point P510 (37.8017, 2.9096)
    point P511 (38.1748, 2.8686)
    point P512 (37.8017, 2.9096)
    point P513 (37.1061, 3.6051)
    point P514 (37.1061, 3.6051)
    point P515 (36.6914, 3.6143)
    point P516 (36.6914, 3.6143)
    point P517 (36.3899, 3.3132)
    point P518 (36.3899, 3.3132)
    point P519 (36.3988, 2.8982)
    point P520 (36.3988, 2.8982)
    point P521 (37.0936, 2.2034)
    point P522 (37.1344, 1.8298)
    point P523 (37.0936, 2.2034)
    point P524 (37.1344, 1.8298)
    point P525 (37.1335, -1.8284)
    point P526 (37.0927, -2.2019)
    point P527 (37.1335, -1.8284)
    point P528 (37.0927, -2.2019)
    point P529 (36.3976, -2.897)
    point P530 (36.3976, -2.897)
    point P531 (36.3887, -3.3119)
    point P532 (36.3887, -3.3119)
    point P533 (36.69, -3.6131)
    point P534 (36.69, -3.6131)
    point P535 (37.1048, -3.604)
    point P536 (37.1048, -3.604)
    point P537 (37.8002, -2.9086)
    point P538 (38.1735, -2.8677)
    point P539 (37.8002, -2.9086)
    point P540 (38.1735, -2.8677)
    point P541 (41.8298, -2.8656)
    point P542 (-13.15, 17)
    point P543 (-26.85, 17)
    point P544 (-26.85, 17)
    point P545 (-29.85, 14)
    point P546 (-29.85, 14)
    point P547 (-29.85, 8.9315)
    point P548 (-29.85, 8.9315)
    point P549 (-29.85, -8.9422)
    point P550 (-29.85, -8.9422)
    point P551 (-29.85, -14)
    point P552 (-29.85, -14)
    point P553 (-26.85, -17)
    point P554 (-26.85, -17)
    point P555 (-13.15, -17)
    point P556 (-13.15, -17)
    point P557 (-10.15, -14)
    point P558 (-10.15, -14)
    point P559 (-10.15, -8.9422)
    point P560 (-10.15, -8.9422)
    point P561 (-10.15, 8.9315)
    point P562 (-10.15, 8.9315)
    point P563 (-10.15, 14)
    point P564 (-10.15, 14)
    point P565 (-13.15, 17)
    reference intersected line E1 through (0, 0) direction (0, 1) from zx-plane
    distance H L83 = 20
    distance L15 E1 = 60
    coincidence: P2 P4, P3 P65, P5 P6, P7 P8, P9 P10, P11 P12, P13 P15, P14 P16, P17 P19, P18 P20, P21 P22, P23 P24, P25 P26, P27 P28, P29 P31, P30 P32, P33 P35, P34 P36, P37 P38, P39 P40, P41 P42, P43 P44, P45 P47, P46 P48, P49 P51, P50 P52, P53 P54, P55 P56, P57 P58, P59 P60, P61 P63, P62 P64, P66 P389, P67 P68, P69 P70, P71 P72, P73 P74, P75 P76, P77 P78, P79 P81, P80 P82, P83 P85, P84 P86, P88 P90, P89 P87, P91 P93, P92 P94, P95 P97, P96 P98, P99 P100, P101 P102, P103 P104, P105 P106, P107 P108, P109 P110, P111 P112, P113 P114, P115 P116, P117 P118, P119 P120, P121 P123, P122 P124, P125 P127, P126 P128, P132 P130, P133 P135, P134 P136, P137 P139, P138 P140, P141 P142, P143 P144, P145 P146, P147 P148, P149 P150, P151 P152, P153 P154, P155 P156, P157 P158, P159 P160, P161 P162, P163 P165, P164 P166, P167 P169, P168 P170, P171 P173, P172 P174, P175 P177, P176 P178, P179 P180, P181 P182, P183 P184, P185 P186, P187 P188, P189 P190, P191 P192, P193 P194, P195 P196, P197 P198, P199 P200, P201 P203, P202 P204, P205 P207, P206 P208, P209 P211, P210 P212, P213 P215, P214 P216, P217 P218, P219 P220, P221 P222, P223 P224, P225 P226, P227 P228, P229 P230, P231 P232, P233 P234, P235 P236, P237 P238, P239 P241, P240 P242, P243 P245, P244 P246, P247 P248, P249 P251, P250 P252, P253 P255, P254 P256, P257 P259, P258 P260, P261 P262, P263 P264, P265 P266, P267 P268, P269 P270, P271 P272, P273 P274, P275 P276, P277 P278, P279 P280, P281 P282, P283 P285, P284 P286, P287 P289, P288 P290, P291 P293, P292 P294, P295 P296, P297 P299, P298 P300, P301 P303, P302 P304, P305 P306, P307 P308, P309 P310, P311 P312, P313 P314, P315 P316, P317 P318, P319 P320, P321 P322, P323 P324, P325 P326, P327 P329, P328 P330, P331 P333, P332 P334, P335 P337, P336 P338, P339 P341, P340 P342, P343 P344, P345 P346, P347 P348, P349 P350, P351 P352, P353 P354, P355 P356, P357 P358, P359 P360, P361 P362, P363 P364, P365 P367, P366 P368, P369 P371, P370 P372, P373 P375, P374 P376, P377 P379, P378 P380, P381 P382, P383 P384, P385 P386, P387 P388, P390 P413, P391 P392, P393 P394, P395 P396, P397 P398, P399 P400, P401 P402, P403 P404, P405 P406, P407 P408, P409 P410, P411 P412, P414 P416, P415 P477, P417 P418, P419 P420, P421 P422, P423 P424, P425 P427, P426 P428, P429 P431, P430 P432, P433 P434, P435 P436, P437 P438, P439 P440, P441 P443, P442 P444, P445 P447, P446 P448, P449 P450, P451 P452, P453 P454, P455 P456, P457 P459, P458 P460, P461 P463, P462 P464, P465 P466, P467 P468, P469 P470, P471 P472, P473 P475, P474 P476, P478 P480, P479 P541, P481 P482, P483 P484, P485 P486, P487 P488, P489 P491, P490 P492, P493 P495, P494 P496, P497 P498, P499 P500, P501 P502, P503 P504, P505 P507, P506 P508, P509 P511, P510 P512, P513 P514, P515 P516, P517 P518, P519 P520, P521 P523, P522 P524, P525 P527, P526 P528, P529 P530, P531 P532, P533 P534, P535 P536, P537 P539, P538 P540, P542 P565, P543 P544, P545 P546, P547 P548, P549 P550, P551 P552, P553 P554, P555 P556, P557 P558, P559 P560, P561 P562, P563 P564, P131 P129
  Pad1: profile Sketch1, direction (1, 0, 0), length 500, mirrored extent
